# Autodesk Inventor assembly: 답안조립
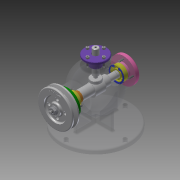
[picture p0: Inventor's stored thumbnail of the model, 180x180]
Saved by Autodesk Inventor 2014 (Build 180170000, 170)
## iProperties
Created: 2020-08
Part Number: 답안조립
Document SubType Name: Assembly
Designer: kh
Author: kh
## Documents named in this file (18)
- C:\Users\kh\Desktop\700806V1030\답안조립.iam
- C:\Users\kh\Desktop\700806V1030\본체.ipt
- C:\Users\kh\Desktop\700806V1030\V-벨트풀리.ipt
- C:\Users\kh\Desktop\700806V1030\너트 M8.ipt
- C:\Users\kh\Desktop\700806V1030\뒤커버.ipt
- C:\Users\kh\Desktop\700806V1030\멈춤링 15x1.ipt
- C:\Users\kh\Desktop\700806V1030\멈춤링 35x1.6.ipt
- 멈춤링 35x1.6.ipt
- C:\Users\kh\Desktop\700806V1030\베어링 6202.ipt
- 베어링 6202.ipt
- C:\Users\kh\Desktop\700806V1030\볼트 M4.ipt
- C:\Users\kh\Desktop\700806V1030\상부커버.ipt
- C:\Users\kh\Desktop\700806V1030\슬라이드.ipt
- C:\Users\kh\Desktop\700806V1030\앞커버.ipt
- C:\Users\kh\Desktop\700806V1030\오일 실 15 30 7.ipt
- C:\Users\kh\Desktop\700806V1030\칼라.ipt
- C:\Users\kh\Desktop\700806V1030\키 3x3x12.ipt
- C:\Users\kh\Desktop\700806V1030\편심축.ipt
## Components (1 placed, 1 different names)
1. V-벨트풀리:1 — Insert:11, Mate:2, Insert:12
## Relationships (3: Insert 2, Mate 1)
- Insert:11: V-벨트풀리:1
- Mate:2: V-벨트풀리:1
- Insert:12: V-벨트풀리:1
